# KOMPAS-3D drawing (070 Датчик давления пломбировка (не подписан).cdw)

Referenced files in \\Promsrv4\спо\002_Проекты (ПСПД)\г. Южно-Сахалинск\Работы по ИТП (COWI) 2014\ПРОЕКТЫ ИТП\Украинская, 9\пломбировка приборов\: Датчик давления пломбировка (не подписан).cdw
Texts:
  ПСПД-0000-2015
  Схема пломбировки  датчика давления мод. ПД-Р
  ГОСТ 16037-80-У17-ЗН- 4
  пломба
  Схема пломбировки
  датчика давления мод. ПД-Р
  ПСПД-0093-2014-
  ЗАО "ПромСервис"
Dimensions and other numbers on the sheet: 33,6; 1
